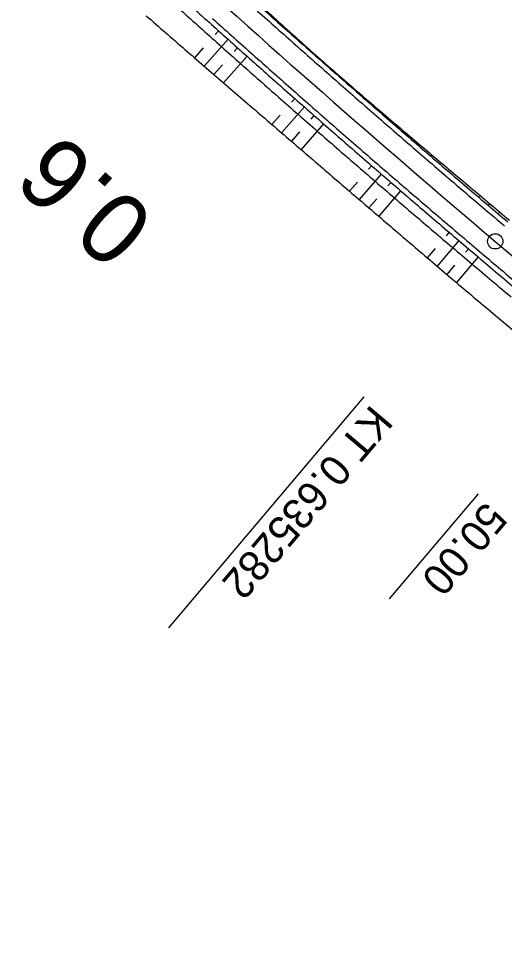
# Model space of a CAD drawing. Extents: x -481645 to -478728, y -1113199 to -1110710.
# Drawn here: x -481310.8 to -481263.1, y -1113096.8 to -1113006.1 of the extents above; entities that cross this region are included whole.
import ezdxf

# ---------------------------------------------------------------- set-up
doc = ezdxf.new("R2010")
doc.units = 0
for name, color, linetype in [('Vrstva 41', 7, 'Continuous'), ('Vrstva 42', 7, 'Continuous'), ('Vrstva 43', 7, 'Continuous'), ('Vrstva 44', 7, 'Continuous'), ('Vrstva 45', 7, 'Continuous'), ('Vrstva 46', 7, 'Continuous'), ('Vrstva 47', 7, 'Continuous'), ('Vrstva 48', 7, 'Continuous'), ('Vrstva 49', 7, 'Continuous'), ('Vrstva 50', 7, 'Continuous'), ('Vrstva 51', 7, 'Continuous')]:
    doc.layers.add(name, color=color, linetype=linetype)

msp = doc.modelspace()

# ---------------------------------------------------------------- linework, layer by layer
at = {"layer": 'Vrstva 41'}
msp.add_line((-481263.983, -1113027.971), (-481182.61, -1113096.802), dxfattribs=at)
msp.add_arc((-480489, -1112111.782), 1200, 227.633469, 229.772919, dxfattribs=at)
at = {"layer": 'Vrstva 42'}
msp.add_line((-481263.952, -1113035.239), (-481260.121, -1113038.453), dxfattribs=at)
for centre, radius, start, end in [((-480481.223, -1112118.795), 1197.641, 227.587328, 227.826069), ((-480504.17, -1112098.337), 1205.863, 228.812678, 229.051444), ((-480484.126, -1112116.126), 1197.677, 228.014683, 228.253419), ((-480504.003, -1112098.593), 1205.78, 229.037497, 229.276264), ((-480491.695, -1112109.42), 1197.683, 228.737172, 228.975906), ((-480503.293, -1112099.312), 1205.698, 229.228419, 229.467183), ((-480497.095, -1112104.789), 1197.653, 229.316253, 229.554994), ((-480499.178, -1112102.936), 1205.631, 229.206586, 229.445333), ((-480497.443, -1112104.552), 1197.607, 229.575008, 229.813753), ((-480494.105, -1112107.357), 1205.589, 229.125553, 229.364289), ((-480497.596, -1112104.484), 1197.561, 229.82145, 230.060194), ((-480493.699, -1112107.742), 1205.562, 229.337739, 229.576475), ((-480493.083, -1112108.328), 1197.526, 229.776553, 230.015289), ((-480489.333, -1112111.496), 1205.548, 229.302819, 229.541553), ((-480488.495, -1112112.211), 1205.548, 229.489211, 229.727944), ((-480878.463, -1112571.843), 602.775, 229.768303, 230.2437)]:
    msp.add_arc(centre, radius, start, end, dxfattribs=at)
at = {"layer": 'Vrstva 43'}
for centre, radius, start, end in [((-480490.048, -1112110.838), 1203.221, 227.916725, 228.155458), ((-480490.35, -1112110.577), 1203.214, 228.174467, 228.4132), ((-480490.366, -1112110.573), 1203.207, 228.4139, 228.652633), ((-480490.368, -1112110.581), 1203.199, 228.652458, 228.891192), ((-480490.376, -1112110.584), 1203.191, 228.891367, 229.1301), ((-480490.381, -1112110.59), 1203.184, 229.1301, 229.368833), ((-480490.386, -1112110.596), 1203.176, 229.368833, 229.607567), ((-480490.394, -1112110.599), 1203.169, 229.607742, 229.846475), ((-480876.516, -1112571.93), 601.582, 229.621411, 230.097692)]:
    msp.add_arc(centre, radius, start, end, dxfattribs=at)
at = {"layer": 'Vrstva 44'}
for centre, radius, start, end in [((-480489, -1112111.782), 1202.25, 227.849589, 228.088322), ((-480489, -1112111.782), 1197.75, 228.088322, 228.327056), ((-480489, -1112111.782), 1202.25, 228.088322, 228.327056), ((-480489, -1112111.782), 1197.75, 228.327056, 228.565789), ((-480489, -1112111.782), 1202.25, 228.327056, 228.565789), ((-480489, -1112111.782), 1197.75, 228.565786, 228.804519), ((-480489, -1112111.782), 1197.75, 228.804519, 229.043253), ((-480489, -1112111.782), 1202.25, 228.565789, 228.804522), ((-480489, -1112111.782), 1202.25, 228.804519, 229.043253), ((-480489, -1112111.782), 1197.75, 229.043253, 229.281986), ((-480489, -1112111.782), 1202.25, 229.043253, 229.281986), ((-480489, -1112111.782), 1197.75, 229.281986, 229.520719), ((-480489, -1112111.782), 1202.25, 229.281986, 229.520719), ((-480489, -1112111.782), 1197.75, 229.520719, 229.759453), ((-480489, -1112111.782), 1202.25, 229.520719, 229.759453), ((-480875.525, -1112572.174), 601.125, 229.534178, 230.0108)]:
    msp.add_arc(centre, radius, start, end, dxfattribs=at)
at = {"layer": 'Vrstva 45'}
for centre, radius, start, end in [((-480489, -1112111.782), 1198.25, 228.088322, 228.327056), ((-480489, -1112111.782), 1201.75, 228.088322, 228.327056), ((-480489, -1112111.782), 1198.25, 228.327056, 228.565789), ((-480489, -1112111.782), 1201.75, 228.327056, 228.565789), ((-480489, -1112111.782), 1198.25, 228.565786, 228.804519), ((-480489, -1112111.782), 1201.75, 228.565789, 228.804522), ((-480489, -1112111.782), 1198.25, 228.804519, 229.043253), ((-480489, -1112111.782), 1201.75, 228.804519, 229.043253), ((-480489, -1112111.782), 1198.25, 229.043253, 229.281986), ((-480489, -1112111.782), 1201.75, 229.043253, 229.281986), ((-480489, -1112111.782), 1198.25, 229.281986, 229.520719), ((-480489, -1112111.782), 1201.75, 229.281986, 229.520719), ((-480489, -1112111.782), 1198.25, 229.520719, 229.759453), ((-480489, -1112111.782), 1201.75, 229.520719, 229.759453), ((-480875.363, -1112571.983), 600.875, 229.534083, 230.010894)]:
    msp.add_arc(centre, radius, start, end, dxfattribs=at)
at = {"layer": 'Vrstva 46'}
for centre, radius, start, end in [((-480489, -1112111.782), 1198.25, 228.088322, 228.327056), ((-480489, -1112111.782), 1201.75, 228.088322, 228.327056), ((-480489, -1112111.782), 1198.25, 228.327056, 228.565789), ((-480489, -1112111.782), 1201.75, 228.327056, 228.565789), ((-480489, -1112111.782), 1198.25, 228.565786, 228.804519), ((-480489, -1112111.782), 1201.75, 228.565789, 228.804522), ((-480489, -1112111.782), 1198.25, 228.804519, 229.043253), ((-480489, -1112111.782), 1201.75, 228.804519, 229.043253), ((-480489, -1112111.782), 1198.25, 229.043253, 229.281986), ((-480489, -1112111.782), 1201.75, 229.043253, 229.281986), ((-480489, -1112111.782), 1198.25, 229.281986, 229.520719), ((-480489, -1112111.782), 1201.75, 229.281986, 229.520719), ((-480489, -1112111.782), 1198.25, 229.520719, 229.759453), ((-480489, -1112111.782), 1201.75, 229.520719, 229.759453), ((-480875.363, -1112571.983), 600.875, 229.534083, 230.010894)]:
    msp.add_arc(centre, radius, start, end, dxfattribs=at)
at = {"layer": 'Vrstva 47'}
msp.add_line((-481265.662, -1113052.746), (-481274.381, -1113063.053), dxfattribs=at)
at = {"layer": 'Vrstva 48'}
msp.add_line((-481276.899, -1113043.241), (-481296.08, -1113065.916), dxfattribs=at)
msp.add_circle((-481263.983, -1113027.971), 0.75, dxfattribs=at)
at = {"layer": 'Vrstva 50'}
for p, q in [((-481285.358, -1113006.444), (-481285.3, -1113006.378)), ((-481280.687, -1113010.579), (-481280.666, -1113010.555)), ((-481280.645, -1113010.531), (-481280.645, -1113010.531)), ((-481279.751, -1113011.403), (-481279.706, -1113011.353)), ((-481278.766, -1113012.173), (-481278.766, -1113012.173)), ((-481278.813, -1113012.226), (-481278.79, -1113012.2)), ((-481277.875, -1113013.049), (-481277.825, -1113012.992)), ((-481273.17, -1113017.145), (-481273.127, -1113017.096)), ((-481273.084, -1113017.046), (-481273.084, -1113017.046)), ((-481272.226, -1113017.962), (-481272.133, -1113017.854)), ((-481271.282, -1113018.777), (-481271.232, -1113018.718)), ((-481271.181, -1113018.66), (-481271.181, -1113018.66)), ((-481270.337, -1113019.591), (-481270.229, -1113019.466)), ((-481265.598, -1113023.648), (-481265.528, -1113023.565)), ((-481265.457, -1113023.482), (-481265.457, -1113023.482)), ((-481264.648, -1113024.457), (-481264.503, -1113024.286)), ((-481263.697, -1113025.264), (-481263.622, -1113025.176)), ((-481263.548, -1113025.089), (-481263.548, -1113025.089))]:
    msp.add_line(p, q, dxfattribs=at)
at = {"layer": 'Vrstva 51'}
for p, q in [((-481291.152, -1113007.302), (-481291.474, -1113007.662)), ((-481290.219, -1113008.138), (-481292.571, -1113010.769)), ((-481292.659, -1113008.984), (-481293.521, -1113009.947)), ((-481289.285, -1113008.972), (-481289.605, -1113009.331)), ((-481288.35, -1113009.805), (-481290.669, -1113012.41)), ((-481290.772, -1113010.64), (-481291.62, -1113011.59)), ((-481283.662, -1113013.956), (-481283.976, -1113014.312)), ((-481282.722, -1113014.783), (-481284.954, -1113017.322)), ((-481285.098, -1113015.586), (-481285.906, -1113016.503)), ((-481281.78, -1113015.609), (-481282.092, -1113015.965)), ((-481280.839, -1113016.435), (-481283.047, -1113018.958)), ((-481283.203, -1113017.231), (-481284.001, -1113018.141)), ((-481276.116, -1113020.547), (-481276.422, -1113020.9)), ((-481275.169, -1113021.366), (-481277.335, -1113023.872)), ((-481277.509, -1113022.154), (-481278.288, -1113023.055)), ((-481273.272, -1113023.002), (-481275.424, -1113025.502)), ((-481274.221, -1113022.184), (-481274.526, -1113022.537)), ((-481275.605, -1113023.788), (-481276.38, -1113024.687)), ((-481268.516, -1113027.074), (-481268.814, -1113027.424)), ((-481267.562, -1113027.886), (-481269.698, -1113030.399)), ((-481269.884, -1113028.68), (-481270.654, -1113029.585)), ((-481266.607, -1113028.696), (-481266.904, -1113029.046)), ((-481267.97, -1113030.304), (-481268.741, -1113031.212)), ((-481265.652, -1113029.506), (-481267.783, -1113032.025))]:
    msp.add_line(p, q, dxfattribs=at)

# ---------------------------------------------------------------- texts
at = {"layer": 'Vrstva 47'}
msp.add_text('50.00', height=3, rotation=229.77293, dxfattribs=at).set_placement((-481264.898, -1113053.391))
at = {"layer": 'Vrstva 48'}
msp.add_text('KT 0.635282', height=2.999, rotation=229.77293, dxfattribs=at).set_placement((-481276.135, -1113043.886))
at = {"layer": 'Vrstva 49'}
msp.add_text('0.6', height=6.999, rotation=138.0427, dxfattribs=at).set_placement((-481297.097, -1113025.829))

doc.saveas('drawing.dxf')
